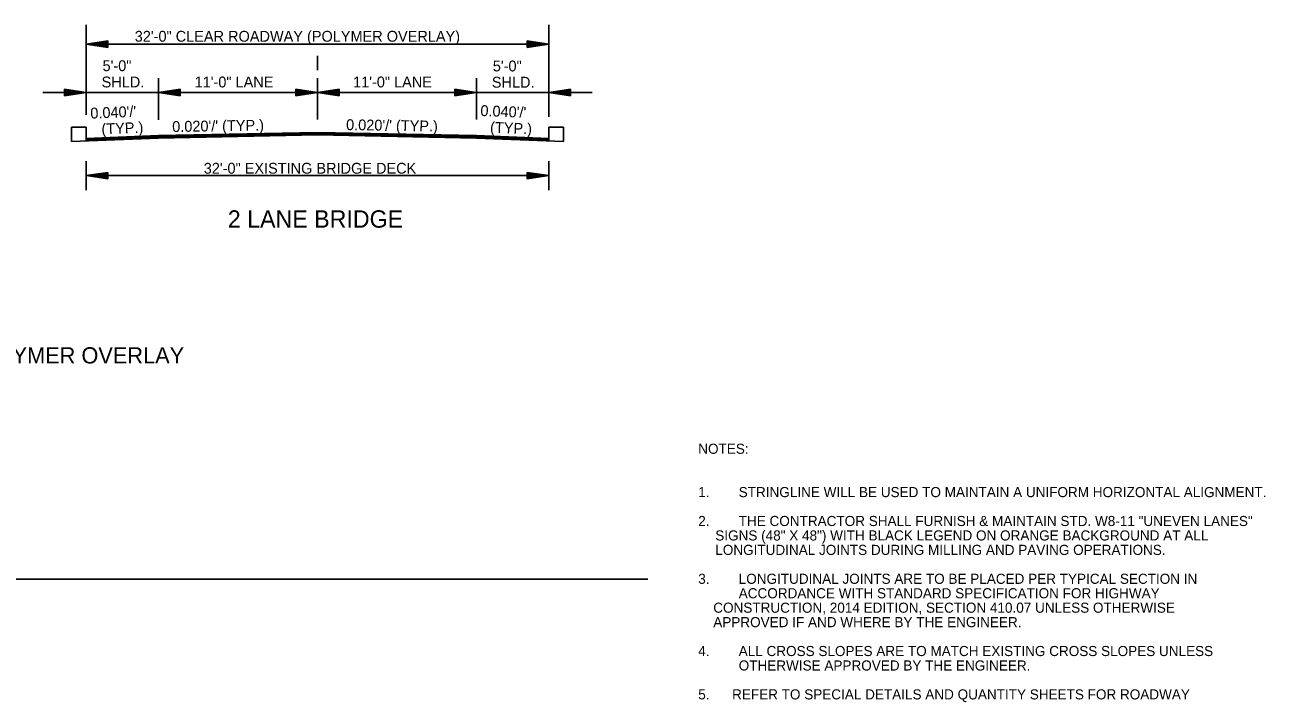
# Model space of a CAD drawing. Extents: x 550980 to 1930787, y -1972975 to 596640.
# Drawn here: x 551641 to 552499, y -1972520 to -1972051 of the extents above; entities that cross this region are included whole.
import ezdxf

# ---------------------------------------------------------------- set-up
doc = ezdxf.new("R2010")
doc.units = 0
for name, color, linetype in [('R_Border', 7, 'Continuous'), ('R_Border Notes', 7, 'Continuous'), ('R_Draft', 7, 'Continuous')]:
    doc.layers.add(name, color=color, linetype=linetype)

msp = doc.modelspace()

# ---------------------------------------------------------------- linework, layer by layer
at = {"layer": 'R_Border'}
for p, q in [((551683.1, -1972121.62), (551672.93, -1972121.62)), ((551672.93, -1972121.62), (551672.93, -1972131.67)), ((551683.1, -1972131.06), (551683.1, -1972121.62)), ((552003.1, -1972131.06), (552003.1, -1972121.62)), ((552003.1, -1972121.62), (552013.26, -1972121.62)), ((552013.26, -1972121.62), (552013.26, -1972131.67)), ((551010.32, -1972434.47), (552071.59, -1972434.47))]:
    msp.add_line(p, q, dxfattribs=at)
at = {"layer": 'R_Draft'}
for p, q in [((551683.1, -1972113.23), (551683.1, -1972050.85)), ((552003.1, -1972114.44), (552003.1, -1972050.85)), ((551698.1, -1972061.97), (551683.1, -1972064.22)), ((551683.1, -1972064.22), (552003.1, -1972064.22)), ((551698.1, -1972066.47), (551683.1, -1972064.22)), ((551698.1, -1972062.34), (551685.6, -1972064.22)), ((551698.1, -1972066.09), (551685.6, -1972064.22)), ((551698.1, -1972062.73), (551688.18, -1972064.22)), ((551698.1, -1972065.71), (551688.18, -1972064.22)), ((551698.1, -1972063.1), (551690.68, -1972064.22)), ((551698.1, -1972065.34), (551690.68, -1972064.22)), ((551698.1, -1972063.48), (551693.22, -1972064.22)), ((551698.1, -1972064.95), (551693.22, -1972064.22)), ((551698.1, -1972063.87), (551695.73, -1972064.22)), ((551698.1, -1972064.57), (551695.73, -1972064.22)), ((551698.1, -1972066.47), (551698.1, -1972061.97)), ((551988.1, -1972061.97), (552003.1, -1972064.22)), ((551988.1, -1972061.97), (551988.1, -1972066.47)), ((551988.1, -1972062.34), (552000.59, -1972064.22)), ((551988.1, -1972062.73), (551998.01, -1972064.22)), ((551988.1, -1972063.1), (551995.51, -1972064.22)), ((551988.1, -1972063.49), (551992.97, -1972064.22)), ((551988.1, -1972063.87), (551990.47, -1972064.22)), ((551988.1, -1972066.47), (552003.1, -1972064.22)), ((551988.1, -1972064.95), (551992.97, -1972064.22)), ((551988.1, -1972065.71), (551998.01, -1972064.22)), ((551988.1, -1972066.09), (552000.59, -1972064.22)), ((551988.1, -1972065.34), (551995.51, -1972064.22)), ((551988.1, -1972064.57), (551990.47, -1972064.22)), ((551843.1, -1972082.16), (551843.1, -1972072.29)), ((551733.1, -1972116.58), (551733.1, -1972087.86)), ((551843.1, -1972116.41), (551843.1, -1972087.86)), ((551953.1, -1972116.41), (551953.1, -1972087.86)), ((551683.1, -1972097.76), (551653.1, -1972097.76)), ((551668.1, -1972095.51), (551683.1, -1972097.76)), ((551668.1, -1972095.51), (551668.1, -1972100.01)), ((551668.1, -1972095.88), (551680.59, -1972097.76)), ((551668.1, -1972096.26), (551678.01, -1972097.76)), ((551668.1, -1972096.64), (551675.51, -1972097.76)), ((551668.1, -1972097.03), (551672.97, -1972097.76)), ((551668.1, -1972097.4), (551670.47, -1972097.76)), ((551668.1, -1972100.01), (551683.1, -1972097.76)), ((551668.1, -1972098.49), (551672.97, -1972097.76)), ((551668.1, -1972099.25), (551678.01, -1972097.76)), ((551668.1, -1972099.63), (551680.59, -1972097.76)), ((551668.1, -1972098.87), (551675.51, -1972097.76)), ((551668.1, -1972098.11), (551670.47, -1972097.76)), ((551733.1, -1972097.76), (551683.1, -1972097.76)), ((551748.1, -1972095.51), (551733.1, -1972097.76)), ((551843.1, -1972097.76), (551733.1, -1972097.76)), ((551748.1, -1972100.01), (551733.1, -1972097.76)), ((551748.1, -1972095.88), (551735.6, -1972097.76)), ((551748.1, -1972099.63), (551735.6, -1972097.76)), ((551748.1, -1972096.26), (551738.18, -1972097.76)), ((551748.1, -1972099.25), (551738.18, -1972097.76)), ((551748.1, -1972096.64), (551740.68, -1972097.76)), ((551748.1, -1972098.87), (551740.68, -1972097.76)), ((551748.1, -1972097.02), (551743.22, -1972097.76)), ((551748.1, -1972098.48), (551743.22, -1972097.76)), ((551748.1, -1972097.4), (551745.73, -1972097.76)), ((551748.1, -1972098.11), (551745.73, -1972097.76)), ((551748.1, -1972100.01), (551748.1, -1972095.51)), ((551828.1, -1972095.51), (551843.1, -1972097.76)), ((551828.1, -1972095.51), (551828.1, -1972100.01)), ((551828.1, -1972095.88), (551840.59, -1972097.76)), ((551828.1, -1972096.26), (551838.01, -1972097.76)), ((551828.1, -1972096.64), (551835.51, -1972097.76)), ((551828.1, -1972097.03), (551832.97, -1972097.76)), ((551828.1, -1972097.4), (551830.47, -1972097.76)), ((551828.1, -1972100.01), (551843.1, -1972097.76)), ((551828.1, -1972098.49), (551832.97, -1972097.76)), ((551828.1, -1972099.25), (551838.01, -1972097.76)), ((551828.1, -1972099.63), (551840.59, -1972097.76)), ((551828.1, -1972098.87), (551835.51, -1972097.76)), ((551828.1, -1972098.11), (551830.47, -1972097.76)), ((551858.1, -1972095.51), (551843.1, -1972097.76)), ((551953.1, -1972097.76), (551843.1, -1972097.76)), ((551858.1, -1972100.01), (551843.1, -1972097.76)), ((551858.1, -1972095.88), (551845.6, -1972097.76)), ((551858.1, -1972099.63), (551845.6, -1972097.76)), ((551858.1, -1972096.26), (551848.18, -1972097.76)), ((551858.1, -1972099.25), (551848.18, -1972097.76)), ((551858.1, -1972096.64), (551850.68, -1972097.76)), ((551858.1, -1972098.87), (551850.68, -1972097.76)), ((551858.1, -1972097.02), (551853.22, -1972097.76)), ((551858.1, -1972098.48), (551853.22, -1972097.76)), ((551858.1, -1972097.4), (551855.73, -1972097.76)), ((551858.1, -1972098.11), (551855.73, -1972097.76)), ((551858.1, -1972100.01), (551858.1, -1972095.51)), ((551938.1, -1972095.51), (551953.1, -1972097.76)), ((551938.1, -1972095.51), (551938.1, -1972100.01)), ((551938.1, -1972095.88), (551950.59, -1972097.76)), ((551938.1, -1972096.26), (551948.01, -1972097.76)), ((551938.1, -1972096.64), (551945.51, -1972097.76)), ((551938.1, -1972097.03), (551942.97, -1972097.76)), ((551938.1, -1972097.4), (551940.47, -1972097.76)), ((551938.1, -1972100.01), (551953.1, -1972097.76)), ((551938.1, -1972098.49), (551942.97, -1972097.76)), ((551938.1, -1972099.25), (551948.01, -1972097.76)), ((551938.1, -1972099.63), (551950.59, -1972097.76)), ((551938.1, -1972098.87), (551945.51, -1972097.76)), ((551938.1, -1972098.11), (551940.47, -1972097.76)), ((552003.1, -1972097.76), (551953.1, -1972097.76)), ((552018.09, -1972095.51), (552003.09, -1972097.76)), ((552018.09, -1972100.01), (552003.09, -1972097.76)), ((552003.09, -1972097.76), (552033.09, -1972097.76)), ((552018.09, -1972095.88), (552005.6, -1972097.76)), ((552018.09, -1972099.63), (552005.6, -1972097.76)), ((552018.09, -1972096.26), (552008.18, -1972097.76)), ((552018.09, -1972099.25), (552008.18, -1972097.76)), ((552018.09, -1972096.64), (552010.68, -1972097.76)), ((552018.09, -1972098.87), (552010.68, -1972097.76)), ((552018.09, -1972097.02), (552013.22, -1972097.76)), ((552018.09, -1972098.48), (552013.22, -1972097.76)), ((552018.09, -1972097.4), (552015.72, -1972097.76)), ((552018.09, -1972098.11), (552015.72, -1972097.76)), ((552018.09, -1972100.01), (552018.09, -1972095.51)), ((551672.93, -1972131.67), (551733.1, -1972129.26)), ((551683.1, -1972129.56), (551733.1, -1972127.56)), ((551683.1, -1972129.86), (551733.1, -1972127.86)), ((551683.1, -1972130.16), (551733.1, -1972128.16)), ((551683.1, -1972130.46), (551733.1, -1972128.46)), ((551683.1, -1972130.76), (551733.1, -1972128.76)), ((551683.1, -1972131.06), (551733.1, -1972129.06)), ((551843.1, -1972125.36), (551733.1, -1972127.56)), ((551843.1, -1972125.66), (551733.1, -1972127.86)), ((551843.11, -1972125.96), (551733.1, -1972128.16)), ((551843.11, -1972126.26), (551733.1, -1972128.46)), ((551843.12, -1972126.56), (551733.1, -1972128.76)), ((551843.13, -1972126.86), (551733.1, -1972129.06)), ((551843.13, -1972127.06), (551733.1, -1972129.26)), ((551843.06, -1972127.06), (551953.1, -1972129.26)), ((551843.07, -1972126.56), (551953.1, -1972128.76)), ((551843.07, -1972126.86), (551953.1, -1972129.06)), ((551843.08, -1972125.96), (551953.1, -1972128.16)), ((551843.08, -1972126.26), (551953.1, -1972128.46)), ((551843.09, -1972125.66), (551953.1, -1972127.86)), ((551843.1, -1972125.36), (551953.1, -1972127.56)), ((552013.26, -1972131.67), (551953.03, -1972129.26)), ((552003.1, -1972131.06), (551953.04, -1972129.06)), ((552003.1, -1972130.76), (551953.05, -1972128.76)), ((552003.1, -1972130.46), (551953.06, -1972128.46)), ((552003.1, -1972130.16), (551953.07, -1972128.16)), ((552003.1, -1972129.86), (551953.08, -1972127.86)), ((552003.1, -1972129.56), (551953.1, -1972127.56)), ((551683.1, -1972145.22), (551683.1, -1972165.22)), ((552003.1, -1972145.22), (552003.1, -1972165.22)), ((551698.1, -1972152.97), (551683.1, -1972155.22)), ((551698.1, -1972153.35), (551685.6, -1972155.22)), ((551698.1, -1972153.73), (551688.18, -1972155.22)), ((551698.1, -1972154.1), (551690.68, -1972155.22)), ((551698.1, -1972154.49), (551693.22, -1972155.22)), ((551698.1, -1972154.87), (551695.73, -1972155.22)), ((551698.1, -1972157.47), (551698.1, -1972152.97)), ((551988.1, -1972152.97), (552003.1, -1972155.22)), ((551988.1, -1972152.97), (551988.1, -1972157.47)), ((551988.1, -1972153.35), (552000.59, -1972155.22)), ((551988.1, -1972153.73), (551998.01, -1972155.22)), ((551988.1, -1972154.1), (551995.51, -1972155.22)), ((551988.1, -1972154.49), (551992.97, -1972155.22)), ((551988.1, -1972154.87), (551990.47, -1972155.22)), ((551683.1, -1972155.22), (552003.1, -1972155.22)), ((551698.1, -1972157.47), (551683.1, -1972155.22)), ((551698.1, -1972157.1), (551685.6, -1972155.22)), ((551698.1, -1972156.71), (551688.18, -1972155.22)), ((551698.1, -1972156.34), (551690.68, -1972155.22)), ((551698.1, -1972155.95), (551693.22, -1972155.22)), ((551698.1, -1972155.57), (551695.73, -1972155.22)), ((551988.1, -1972157.47), (552003.1, -1972155.22)), ((551988.1, -1972155.96), (551992.97, -1972155.22)), ((551988.1, -1972156.71), (551998.01, -1972155.22)), ((551988.1, -1972157.1), (552000.59, -1972155.22)), ((551988.1, -1972156.34), (551995.51, -1972155.22)), ((551988.1, -1972155.57), (551990.47, -1972155.22))]:
    msp.add_line(p, q, dxfattribs=at)

# ---------------------------------------------------------------- texts
at = {"layer": 'R_Border Notes'}
for s, p in [('NOTES: ', (552106.47, -1972347.78)), ('1.', (552106.47, -1972377.78)), ('STRINGLINE WILL BE USED TO MAINTAIN A UNIFORM HORIZONTAL ALIGNMENT.', (552134.47, -1972377.78)), ('2.', (552106.47, -1972397.78)), ('THE CONTRACTOR SHALL FURNISH & MAINTAIN STD. W8-11 "UNEVEN LANES" ', (552134.47, -1972397.78)), ('    SIGNS (48" X 48") WITH BLACK LEGEND ON ORANGE BACKGROUND AT ALL ', (552107.87, -1972407.78)), ('    LONGITUDINAL JOINTS DURING MILLING AND PAVING OPERATIONS.', (552107.87, -1972417.78)), ('3.', (552106.47, -1972437.78)), ('LONGITUDINAL JOINTS ARE TO BE PLACED PER TYPICAL SECTION IN ', (552134.47, -1972437.78)), ('ACCORDANCE WITH STANDARD SPECIFICATION FOR HIGHWAY', (552134.47, -1972447.78)), ('    CONSTRUCTION, 2014 EDITION, SECTION 410.07 UNLESS OTHERWISE', (552106.47, -1972457.78)), ('    APPROVED IF AND WHERE BY THE ENGINEER.', (552106.47, -1972467.78)), ('4.', (552106.47, -1972487.78)), ('ALL CROSS SLOPES ARE TO MATCH EXISTING CROSS SLOPES UNLESS ', (552134.47, -1972487.78)), ('OTHERWISE APPROVED BY THE ENGINEER.', (552134.47, -1972497.78)), ('5.      REFER TO SPECIAL DETAILS AND QUANTITY SHEETS FOR ROADWAY', (552106.47, -1972517.78))]:
    msp.add_text(s, height=7, dxfattribs=at).set_placement(p)
at = {"layer": 'R_Draft'}
for s, height, p in [('32\'-0" CLEAR ROADWAY (POLYMER OVERLAY)', 7.5, (551716.63, -1972062.55)), ('5\'-0"', 7.5, (551694.36, -1972082.93)), ('5\'-0"', 7.5, (551964.36, -1972083.1)), ('SHLD.', 7.5, (551693.69, -1972094.18)), ('11\'-0" LANE', 7.5, (551758.04, -1972094.18)), ('11\'-0" LANE', 7.5, (551867.69, -1972094.18)), ('SHLD.', 7.5, (551963.69, -1972094.35)), ('32\'-0" EXISTING BRIDGE DECK', 7.5, (551764.37, -1972153.9)), ('2 LANE BRIDGE', 12, (551781.01, -1972191.26)), ('32 FT. CLEAR ROADWAY BRIDGE - POLYMER OVERLAY', 11.25, (551347.04, -1972285.27))]:
    msp.add_text(s, height=height, dxfattribs=at).set_placement(p)
for s, rotation, p in [("0.040'/' ", 2.44797, (551686.06, -1972115.81)), ("0.040'/' ", 357.55203, (551955.64, -1972113.9)), ('(TYP.)', 2.44797, (551693.74, -1972126.74)), ("0.020'/' (TYP.)", 0.97192, (551742.62, -1972125.06)), ("0.020'/' (TYP.)", 359.02808, (551862.8, -1972123.69)), ('(TYP.)', 357.55203, (551962.36, -1972125.45))]:
    msp.add_text(s, height=7.5, rotation=rotation, dxfattribs=at).set_placement(p)

doc.saveas('drawing.dxf')
